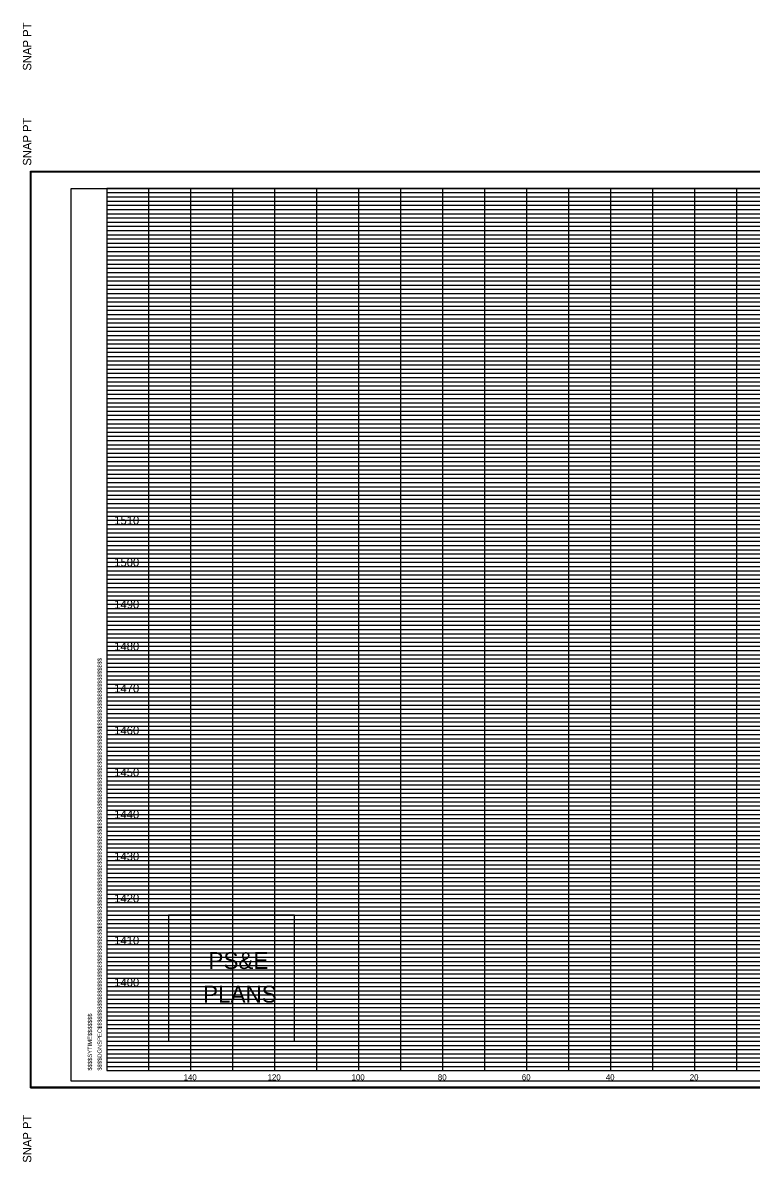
# Model space of a CAD drawing. Extents: x 980 to 2064, y 978 to 2267.
# Drawn here: x 1349.9 to 1523.4, y 978.2 to 1249.4 of the extents above; entities that cross this region are included whole.
import ezdxf

# ---------------------------------------------------------------- set-up
doc = ezdxf.new("R2010")
doc.units = 0
for name, color, linetype in [('Default', 7, 'Continuous'), ('DESIGN - SHEET - Corner Text', 7, 'Continuous'), ('DESIGN - SHEET - Light Grid', 7, 'Continuous'), ('DESIGN - SHEET - Linework', 7, 'Continuous'), ('DESIGN - SHEET - Plot Shape', 7, 'Continuous')]:
    doc.layers.add(name, color=color, linetype=linetype)

# ---------------------------------------------------------------- blocks, each defined once
blk = doc.blocks.new('XSTSHT')
at = {"layer": 'DESIGN - SHEET - Light Grid'}
for p, q in [((0, 20.9), (8, 20.9)), ((8, 20.9), (16, 20.9)), ((0, 20.8), (8, 20.8)), ((0, 20.7), (8, 20.7)), ((8, 20.8), (16, 20.8)), ((8, 20.7), (16, 20.7)), ((0, 20.6), (8, 20.6)), ((0, 20.5), (8, 20.5)), ((0, 20.4), (8, 20.4)), ((8, 20.6), (16, 20.6)), ((8, 20.5), (16, 20.5)), ((8, 20.4), (16, 20.4)), ((0, 20.3), (8, 20.3)), ((0, 20.2), (8, 20.2)), ((0, 20.1), (8, 20.1)), ((8, 20.3), (16, 20.3)), ((8, 20.2), (16, 20.2)), ((8, 20.1), (16, 20.1)), ((0, 19.9), (8, 19.9)), ((8, 19.9), (16, 19.9)), ((0, 19.8), (8, 19.8)), ((0, 19.7), (8, 19.7)), ((0, 19.6), (8, 19.6)), ((8, 19.8), (16, 19.8)), ((8, 19.7), (16, 19.7)), ((8, 19.6), (16, 19.6)), ((0, 19.5), (8, 19.5)), ((0, 19.4), (8, 19.4)), ((0, 19.3), (8, 19.3)), ((8, 19.5), (16, 19.5)), ((8, 19.4), (16, 19.4)), ((8, 19.3), (16, 19.3)), ((0, 19.2), (8, 19.2)), ((0, 19.1), (8, 19.1)), ((8, 19.2), (16, 19.2)), ((8, 19.1), (16, 19.1)), ((0, 18.9), (8, 18.9)), ((0, 18.8), (8, 18.8)), ((8, 18.9), (16, 18.9)), ((8, 18.8), (16, 18.8)), ((0, 18.7), (8, 18.7)), ((0, 18.6), (8, 18.6)), ((0, 18.5), (8, 18.5)), ((8, 18.7), (16, 18.7)), ((8, 18.6), (16, 18.6)), ((8, 18.5), (16, 18.5)), ((0, 18.4), (8, 18.4)), ((0, 18.3), (8, 18.3)), ((0, 18.2), (8, 18.2)), ((8, 18.4), (16, 18.4)), ((8, 18.3), (16, 18.3)), ((8, 18.2), (16, 18.2)), ((0, 18.1), (8, 18.1)), ((8, 18.1), (16, 18.1)), ((0, 17.9), (8, 17.9)), ((0, 17.8), (8, 17.8)), ((0, 17.7), (8, 17.7)), ((8, 17.9), (16, 17.9)), ((8, 17.8), (16, 17.8)), ((8, 17.7), (16, 17.7)), ((0, 17.6), (8, 17.6)), ((0, 17.5), (8, 17.5)), ((0, 17.4), (8, 17.4)), ((8, 17.6), (16, 17.6)), ((8, 17.5), (16, 17.5)), ((8, 17.4), (16, 17.4)), ((0, 17.3), (8, 17.3)), ((0, 17.2), (8, 17.2)), ((0, 17.1), (8, 17.1)), ((8, 17.3), (16, 17.3)), ((8, 17.2), (16, 17.2)), ((8, 17.1), (16, 17.1)), ((0, 16.9), (8, 16.9)), ((8, 16.9), (16, 16.9)), ((0, 16.8), (8, 16.8)), ((0, 16.7), (8, 16.7)), ((0, 16.6), (8, 16.6)), ((8, 16.8), (16, 16.8)), ((8, 16.7), (16, 16.7)), ((8, 16.6), (16, 16.6)), ((0, 16.5), (8, 16.5)), ((0, 16.4), (8, 16.4)), ((0, 16.3), (8, 16.3)), ((8, 16.5), (16, 16.5)), ((8, 16.4), (16, 16.4)), ((8, 16.3), (16, 16.3)), ((0, 16.2), (8, 16.2)), ((0, 16.1), (8, 16.1)), ((8, 16.2), (16, 16.2)), ((8, 16.1), (16, 16.1)), ((0, 15.9), (8, 15.9)), ((0, 15.8), (8, 15.8)), ((8, 15.9), (16, 15.9)), ((8, 15.8), (16, 15.8)), ((0, 15.7), (8, 15.7)), ((0, 15.6), (8, 15.6)), ((0, 15.5), (8, 15.5)), ((8, 15.7), (16, 15.7)), ((8, 15.6), (16, 15.6)), ((8, 15.5), (16, 15.5)), ((0, 15.4), (8, 15.4)), ((0, 15.3), (8, 15.3)), ((0, 15.2), (8, 15.2)), ((8, 15.4), (16, 15.4)), ((8, 15.3), (16, 15.3)), ((8, 15.2), (16, 15.2)), ((0, 15.1), (8, 15.1)), ((8, 15.1), (16, 15.1)), ((0, 14.9), (8, 14.9)), ((0, 14.8), (8, 14.8)), ((0, 14.7), (8, 14.7)), ((8, 14.9), (16, 14.9)), ((8, 14.8), (16, 14.8)), ((8, 14.7), (16, 14.7)), ((0, 14.6), (8, 14.6)), ((0, 14.5), (8, 14.5)), ((0, 14.4), (8, 14.4)), ((8, 14.6), (16, 14.6)), ((8, 14.5), (16, 14.5)), ((8, 14.4), (16, 14.4)), ((0, 14.3), (8, 14.3)), ((0, 14.2), (8, 14.2)), ((8, 14.3), (16, 14.3)), ((8, 14.2), (16, 14.2)), ((0, 14.1), (8, 14.1)), ((0, 13.9), (8, 13.9)), ((8, 14.1), (16, 14.1)), ((8, 13.9), (16, 13.9)), ((0, 13.8), (8, 13.8)), ((0, 13.7), (8, 13.7)), ((0, 13.6), (8, 13.6)), ((8, 13.8), (16, 13.8)), ((8, 13.7), (16, 13.7)), ((8, 13.6), (16, 13.6)), ((0, 13.5), (8, 13.5)), ((0, 13.4), (8, 13.4)), ((0, 13.3), (8, 13.3)), ((8, 13.5), (16, 13.5)), ((8, 13.4), (16, 13.4)), ((8, 13.3), (16, 13.3)), ((0, 13.2), (8, 13.2)), ((0, 13.1), (8, 13.1)), ((8, 13.2), (16, 13.2)), ((8, 13.1), (16, 13.1)), ((0, 12.9), (8, 12.9)), ((0, 12.8), (8, 12.8)), ((8, 12.9), (16, 12.9)), ((8, 12.8), (16, 12.8)), ((0, 12.7), (8, 12.7)), ((0, 12.6), (8, 12.6)), ((0, 12.5), (8, 12.5)), ((8, 12.7), (16, 12.7)), ((8, 12.6), (16, 12.6)), ((8, 12.5), (16, 12.5)), ((0, 12.4), (8, 12.4)), ((0, 12.3), (8, 12.3)), ((8, 12.4), (16, 12.4)), ((8, 12.3), (16, 12.3)), ((0, 12.2), (8, 12.2)), ((0, 12.1), (8, 12.1)), ((8, 12.2), (16, 12.2)), ((8, 12.1), (16, 12.1)), ((0, 11.9), (8, 11.9)), ((0, 11.8), (8, 11.8)), ((0, 11.7), (8, 11.7)), ((8, 11.9), (16, 11.9)), ((8, 11.8), (16, 11.8)), ((8, 11.7), (16, 11.7)), ((0, 11.6), (8, 11.6)), ((0, 11.5), (8, 11.5)), ((0, 11.4), (8, 11.4)), ((8, 11.6), (16, 11.6)), ((8, 11.5), (16, 11.5)), ((8, 11.4), (16, 11.4)), ((0, 11.3), (8, 11.3)), ((0, 11.2), (8, 11.2)), ((8, 11.3), (16, 11.3)), ((8, 11.2), (16, 11.2)), ((0, 11.1), (8, 11.1)), ((0, 10.9), (8, 10.9)), ((8, 11.1), (16, 11.1)), ((8, 10.9), (16, 10.9)), ((0, 10.8), (8, 10.8)), ((0, 10.7), (8, 10.7)), ((0, 10.6), (8, 10.6)), ((8, 10.8), (16, 10.8)), ((8, 10.7), (16, 10.7)), ((8, 10.6), (16, 10.6)), ((0, 10.5), (8, 10.5)), ((0, 10.4), (8, 10.4)), ((8, 10.5), (16, 10.5)), ((8, 10.4), (16, 10.4)), ((0, 10.3), (8, 10.3)), ((0, 10.2), (8, 10.2)), ((0, 10.1), (8, 10.1)), ((8, 10.3), (16, 10.3)), ((8, 10.2), (16, 10.2)), ((8, 10.1), (16, 10.1)), ((0, 9.9), (8, 9.9)), ((0, 9.8), (8, 9.8)), ((8, 9.9), (16, 9.9)), ((8, 9.8), (16, 9.8)), ((0, 9.7), (8, 9.7)), ((0, 9.6), (8, 9.6)), ((0, 9.5), (8, 9.5)), ((8, 9.7), (16, 9.7)), ((8, 9.6), (16, 9.6)), ((8, 9.5), (16, 9.5)), ((0, 9.4), (8, 9.4)), ((0, 9.3), (8, 9.3)), ((8, 9.4), (16, 9.4)), ((8, 9.3), (16, 9.3)), ((0, 9.2), (8, 9.2)), ((0, 9.1), (8, 9.1)), ((8, 9.2), (16, 9.2)), ((8, 9.1), (16, 9.1)), ((0, 8.9), (8, 8.9)), ((0, 8.8), (8, 8.8)), ((0, 8.7), (8, 8.7)), ((8, 8.9), (16, 8.9)), ((8, 8.8), (16, 8.8)), ((8, 8.7), (16, 8.7)), ((0, 8.6), (8, 8.6)), ((0, 8.5), (8, 8.5)), ((8, 8.6), (16, 8.6)), ((8, 8.5), (16, 8.5)), ((0, 8.4), (8, 8.4)), ((0, 8.3), (8, 8.3)), ((0, 8.2), (8, 8.2)), ((8, 8.4), (16, 8.4)), ((8, 8.3), (16, 8.3)), ((8, 8.2), (16, 8.2)), ((0, 8.1), (8, 8.1)), ((0, 7.9), (8, 7.9)), ((8, 8.1), (16, 8.1)), ((8, 7.9), (16, 7.9)), ((0, 7.8), (8, 7.8)), ((0, 7.7), (8, 7.7)), ((0, 7.6), (8, 7.6)), ((8, 7.8), (16, 7.8)), ((8, 7.7), (16, 7.7)), ((8, 7.6), (16, 7.6)), ((0, 7.5), (8, 7.5)), ((0, 7.4), (8, 7.4)), ((8, 7.5), (16, 7.5)), ((8, 7.4), (16, 7.4)), ((0, 7.3), (8, 7.3)), ((0, 7.2), (8, 7.2)), ((0, 7.1), (8, 7.1)), ((8, 7.3), (16, 7.3)), ((8, 7.2), (16, 7.2)), ((8, 7.1), (16, 7.1)), ((0, 6.9), (8, 6.9)), ((0, 6.8), (8, 6.8)), ((8, 6.9), (16, 6.9)), ((8, 6.8), (16, 6.8)), ((0, 6.7), (8, 6.7)), ((0, 6.6), (8, 6.6)), ((8, 6.7), (16, 6.7)), ((8, 6.6), (16, 6.6)), ((0, 6.5), (8, 6.5)), ((0, 6.4), (8, 6.4)), ((0, 6.3), (8, 6.3)), ((8, 6.5), (16, 6.5)), ((8, 6.4), (16, 6.4)), ((8, 6.3), (16, 6.3)), ((0, 6.2), (8, 6.2)), ((0, 6.1), (8, 6.1)), ((8, 6.2), (16, 6.2)), ((8, 6.1), (16, 6.1)), ((0, 5.9), (8, 5.9)), ((0, 5.8), (8, 5.8)), ((0, 5.7), (8, 5.7)), ((8, 5.9), (16, 5.9)), ((8, 5.8), (16, 5.8)), ((8, 5.7), (16, 5.7)), ((0, 5.6), (8, 5.6)), ((0, 5.5), (8, 5.5)), ((8, 5.6), (16, 5.6)), ((8, 5.5), (16, 5.5)), ((0, 5.4), (8, 5.4)), ((0, 5.3), (8, 5.3)), ((0, 5.2), (8, 5.2)), ((8, 5.4), (16, 5.4)), ((8, 5.3), (16, 5.3)), ((8, 5.2), (16, 5.2)), ((0, 5.1), (8, 5.1)), ((0, 4.9), (8, 4.9)), ((8, 5.1), (16, 5.1)), ((8, 4.9), (16, 4.9)), ((0, 4.8), (8, 4.8)), ((0, 4.7), (8, 4.7)), ((8, 4.8), (16, 4.8)), ((8, 4.7), (16, 4.7)), ((0, 4.6), (8, 4.6)), ((0, 4.5), (8, 4.5)), ((0, 4.4), (8, 4.4)), ((8, 4.6), (16, 4.6)), ((8, 4.5), (16, 4.5)), ((8, 4.4), (16, 4.4)), ((0, 4.3), (8, 4.3)), ((0, 4.2), (8, 4.2)), ((0, 4.1), (8, 4.1)), ((8, 4.3), (16, 4.3)), ((8, 4.2), (16, 4.2)), ((8, 4.1), (16, 4.1)), ((0, 3.9), (8, 3.9)), ((0, 3.8), (8, 3.8)), ((8, 3.9), (16, 3.9)), ((8, 3.8), (16, 3.8)), ((0, 3.7), (8, 3.7)), ((0, 3.6), (8, 3.6)), ((8, 3.7), (16, 3.7)), ((8, 3.6), (16, 3.6)), ((0, 3.5), (8, 3.5)), ((0, 3.4), (8, 3.4)), ((0, 3.3), (8, 3.3)), ((8, 3.5), (16, 3.5)), ((8, 3.4), (16, 3.4)), ((8, 3.3), (16, 3.3)), ((0, 3.2), (8, 3.2)), ((0, 3.1), (8, 3.1)), ((8, 3.2), (16, 3.2)), ((8, 3.1), (16, 3.1)), ((0, 2.9), (8, 2.9)), ((0, 2.8), (8, 2.8)), ((8, 2.9), (16, 2.9)), ((8, 2.8), (16, 2.8)), ((0, 2.7), (8, 2.7)), ((0, 2.6), (8, 2.6)), ((0, 2.5), (8, 2.5)), ((8, 2.7), (16, 2.7)), ((8, 2.6), (16, 2.6)), ((8, 2.5), (16, 2.5)), ((0, 2.4), (8, 2.4)), ((0, 2.3), (8, 2.3)), ((0, 2.2), (8, 2.2)), ((8, 2.4), (16, 2.4)), ((8, 2.3), (16, 2.3)), ((8, 2.2), (16, 2.2)), ((0, 2.1), (8, 2.1)), ((0, 1.9), (8, 1.9)), ((8, 2.1), (16, 2.1)), ((8, 1.9), (16, 1.9)), ((0, 1.8), (8, 1.8)), ((0, 1.7), (8, 1.7)), ((8, 1.8), (16, 1.8)), ((8, 1.7), (16, 1.7)), ((0, 1.6), (8, 1.6)), ((0, 1.5), (8, 1.5)), ((0, 1.4), (8, 1.4)), ((8, 1.6), (16, 1.6)), ((8, 1.5), (16, 1.5)), ((8, 1.4), (16, 1.4)), ((0, 1.3), (8, 1.3)), ((0, 1.2), (8, 1.2)), ((0, 1.1), (8, 1.1)), ((8, 1.3), (16, 1.3)), ((8, 1.2), (16, 1.2)), ((8, 1.1), (16, 1.1)), ((0, 0.9), (8, 0.9)), ((8, 0.9), (16, 0.9)), ((0, 0.8), (8, 0.8)), ((0, 0.7), (8, 0.7)), ((0, 0.6), (8, 0.6)), ((8, 0.8), (16, 0.8)), ((8, 0.7), (16, 0.7)), ((8, 0.6), (16, 0.6)), ((0, 0.5), (8, 0.5)), ((0, 0.4), (8, 0.4)), ((0, 0.3), (8, 0.3)), ((8, 0.5), (16, 0.5)), ((8, 0.4), (16, 0.4)), ((8, 0.3), (16, 0.3)), ((0, 0.2), (8, 0.2)), ((0, 0.1), (8, 0.1)), ((8, 0.2), (16, 0.2)), ((8, 0.1), (16, 0.1))]:
    blk.add_line(p, q, dxfattribs=at)
at = {"layer": 'DESIGN - SHEET - Linework'}
for p, q in [((-1.823, -0.414), (-1.823, 21.414)), ((-1.823, 21.414), (32.217, 21.414)), ((1, 0), (1, 21)), ((2, 0), (2, 21)), ((3, 0), (3, 21)), ((4, 0), (4, 21)), ((5, 0), (5, 21)), ((6, 0), (6, 21)), ((7, 0), (7, 21)), ((8, 0), (8, 21)), ((9, 0), (9, 21)), ((10, 0), (10, 21)), ((11, 0), (11, 21)), ((12, 0), (12, 21)), ((13, 0), (13, 21)), ((14, 0), (14, 21)), ((15, 0), (15, 21)), ((0, 20), (28, 20)), ((0, 19), (32, 19)), ((0, 18), (32, 18)), ((0, 17), (32, 17)), ((0, 16), (32, 16)), ((0, 15), (32, 15)), ((0, 14), (32, 14)), ((0, 13), (32, 13)), ((0, 12), (32, 12)), ((0, 11), (32, 11)), ((0, 10), (32, 10)), ((0, 9), (32, 9)), ((0, 8), (32, 8)), ((0, 7), (32, 7)), ((0, 6), (32, 6)), ((0, 5), (32, 5)), ((0, 4), (32, 4)), ((0, 3), (32, 3)), ((0, 2), (32, 2)), ((0, 1), (32, 1)), ((-1.823, -0.414), (32.217, -0.414))]:
    blk.add_line(p, q, dxfattribs=at)
blk.add_lwpolyline([(0, 21), (0, 0), (32, 0), (32, 21), (0, 21)], dxfattribs=at)
at = {"layer": 'DESIGN - SHEET - Plot Shape'}
for points in [[(-1.803, 21.394), (32.197, 21.394), (32.197, -0.394), (-1.803, -0.394)], [(-0.85, 21), (32, 21), (32, -0.25), (-0.85, -0.25)]]:
    blk.add_lwpolyline(points, close=True, dxfattribs=at)
at = {"layer": 'DESIGN - SHEET - Corner Text'}
for s, height, p in [('  SNAP PT', 0.2, (-1.803, 21.394)), ('$$$$DGNSPEC$$$$$$$$$$$$$$$$$$$$$$$$$$$$$$$$$$$$$$$$$$$$$$$$$$$$$$$$$$$$$$$$$$$$$$$$$$$$$$$$$$$$$$$$$$$$$$$$$$$$$$$$$$$$$$$$$$$', 0.100002, (-0.126, 0)), ('$$$$SYTIME$$$$$$$', 0.1, (-0.358, 0)), ('SNAP PT  ', 0.2, (-1.803, -2.194))]:
    blk.add_text(s, height=height, rotation=90, dxfattribs=at).set_placement(p)

msp = doc.modelspace()

# ---------------------------------------------------------------- linework, layer by layer
at = {"layer": 'DESIGN - SHEET - Corner Text'}
msp.add_lwpolyline([(1384.64, 1037.01), (1384.64, 1007.01), (1414.64, 1007.01), (1414.64, 1037.01)], close=True, dxfattribs=at)

# ---------------------------------------------------------------- block references
at = {"layer": 'Default', "xscale": 10, "yscale": 10}
msp.add_blockref('XSTSHT', (1370, 1000), dxfattribs=at)

# ---------------------------------------------------------------- texts
at = {"layer": 'Default'}
for s, height, p in [('     1510     ', 2, (1368.01, 1130)), ('     1500     ', 2, (1368.01, 1120)), ('     1490     ', 2, (1368.01, 1110)), ('     1480     ', 2, (1368.01, 1100)), ('     1470     ', 2, (1368.01, 1090)), ('     1460     ', 2, (1368.01, 1080)), ('     1450     ', 2, (1368.01, 1070)), ('     1440     ', 2, (1368.01, 1060)), ('     1430     ', 2, (1368.01, 1050)), ('     1420     ', 2, (1368.01, 1040)), ('     1410     ', 2, (1368.01, 1030)), ('     1400     ', 2, (1368.01, 1020)), ('     140     ', 1.4, (1385.65, 997.7)), ('     120     ', 1.4, (1405.65, 997.7)), ('     100     ', 1.4, (1425.65, 997.7)), ('     80     ', 1.4, (1446.2, 997.7)), ('     60     ', 1.4, (1466.2, 997.7)), ('     40     ', 1.4, (1486.2, 997.7)), ('     20     ', 1.4, (1506.2, 997.7))]:
    msp.add_text(s, height=height, dxfattribs=at).set_placement(p)
at = {"layer": 'DESIGN - SHEET - Corner Text'}
msp.add_text('SNAP PT  ', height=2, rotation=90, dxfattribs=at).set_placement((1351.97, 1238.06))
for s, p in [('PS&E', (1394.16, 1024.19)), ('PLANS', (1392.88, 1016.19))]:
    msp.add_text(s, height=4, dxfattribs=at).set_placement(p)

doc.saveas('drawing.dxf')
